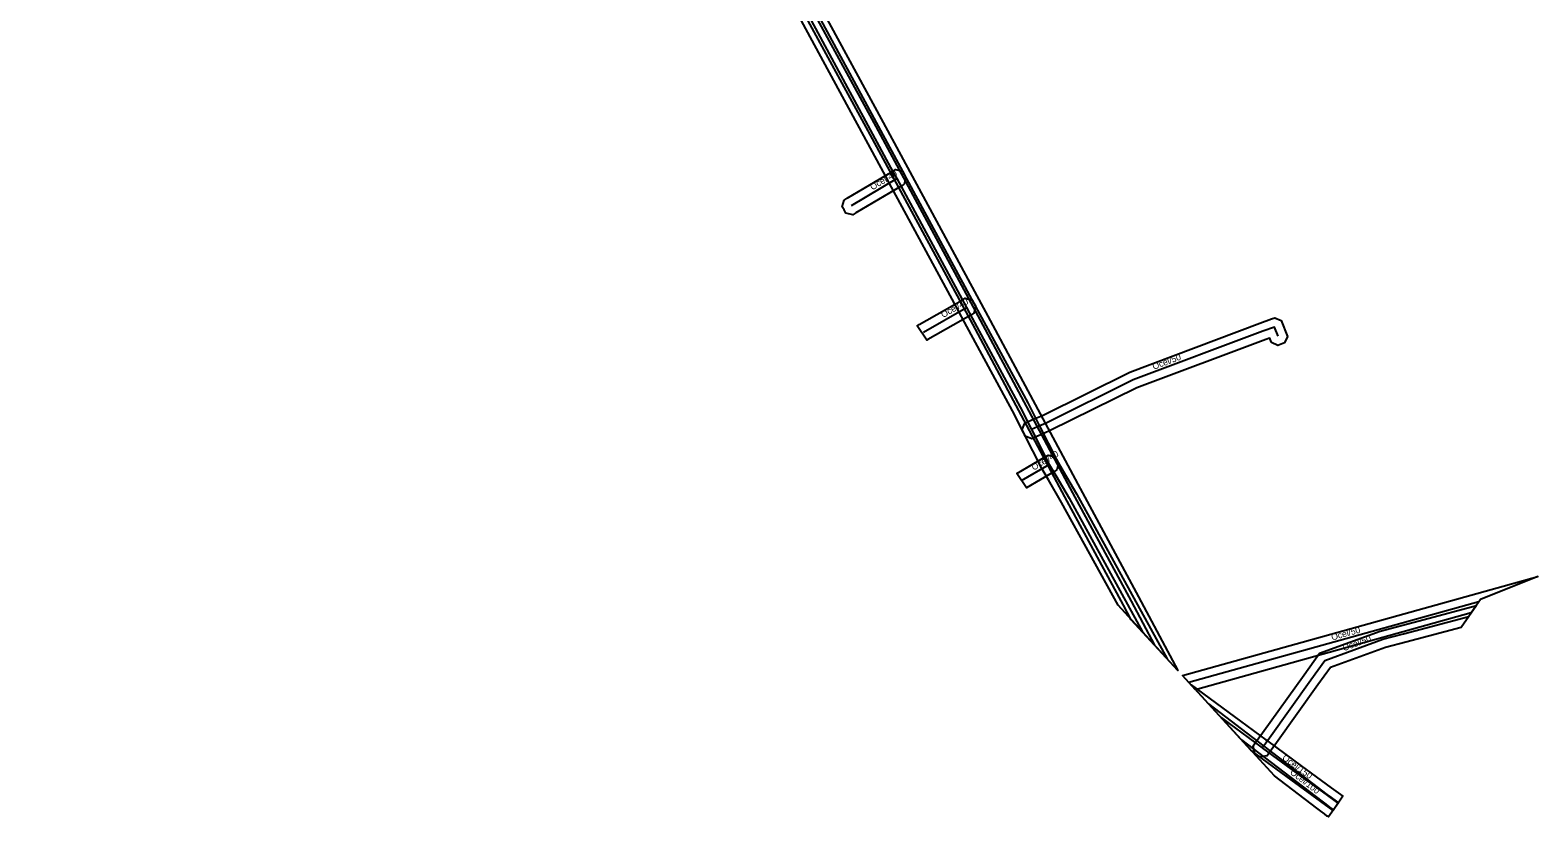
# Model space of a CAD drawing. Extents: x -749340 to -748632, y -965391 to -964902.
# Drawn here: x -748807.4 to -748632.1, y -965391.4 to -965299.9 of the extents above; entities that cross this region are included whole.
import ezdxf

# ---------------------------------------------------------------- set-up
doc = ezdxf.new("R2010")
doc.units = 0
for name, color, linetype in [('1', 7, 'Continuous'), ('18', 7, 'Continuous'), ('20', 7, 'Continuous'), ('28', 7, 'Continuous'), ('30', 7, 'Continuous')]:
    doc.layers.add(name, color=color, linetype=linetype)

msp = doc.modelspace()

# ---------------------------------------------------------------- linework, layer by layer
at = {"layer": '1'}
for points in [[(-748716.01, -965297.73), (-748706.19, -965315.89), (-748705.75, -965316.7), (-748697.65, -965331.68), (-748696.99, -965332.9), (-748691.39, -965343.25), (-748690.06, -965345.87), (-748688.01, -965349.91), (-748687.26, -965351.19), (-748685.72, -965353.82), (-748675.2, -965372.98), (-748680.9, -965366.77), (-748687.46, -965354.81), (-748688.99, -965352.2), (-748689.76, -965350.87), (-748691.84, -965346.78), (-748693.16, -965344.18), (-748698.75, -965333.85), (-748699.41, -965332.63), (-748707.51, -965317.65), (-748707.95, -965316.84), (-748717.7, -965298.81)], [(-748715.47, -965297.31), (-748708.2, -965310.65), (-748696.03, -965333.14), (-748685.32, -965353.2), (-748678.5, -965365.8), (-748673.94, -965374.35), (-748679.36, -965368.45), (-748680.26, -965366.75), (-748687.08, -965354.15), (-748697.8, -965334.09), (-748709.95, -965311.6), (-748717.16, -965298.4)]]:
    msp.add_lwpolyline(points, dxfattribs=at)
for points in [[(-748712.76, -965319.66), (-748712.4, -965319.44), (-748707.14, -965316.32), (-748706.79, -965316.1), (-748705.98, -965316.31), (-748705.77, -965316.66), (-748705.56, -965317.02), (-748705.76, -965317.82), (-748706.12, -965318.03), (-748711.38, -965321.16), (-748711.73, -965321.37), (-748712.54, -965321.17), (-748712.75, -965320.81), (-748712.96, -965320.46)], [(-748703.03, -965335.88), (-748703.12, -965335.93), (-748704.25, -965334.27), (-748704.02, -965334.14), (-748699.02, -965331.29), (-748698.66, -965331.08), (-748697.86, -965331.3), (-748697.66, -965331.66), (-748697.45, -965332.02), (-748697.67, -965332.82), (-748698.03, -965333.03)], [(-748663.07, -965336.23), (-748663.22, -965335.84), (-748663.27, -965335.7), (-748663.7, -965335.86), (-748678.72, -965341.48), (-748688.85, -965346.5), (-748689.86, -965346.94), (-748690.55, -965347.24), (-748690.93, -965347.41), (-748691.7, -965347.11), (-748691.87, -965346.73), (-748692.03, -965346.35), (-748691.73, -965345.58), (-748691.35, -965345.41), (-748690.66, -965345.11), (-748689.69, -965344.69), (-748679.52, -965339.65), (-748664.4, -965333.99), (-748663.05, -965333.48), (-748662.66, -965333.34), (-748661.91, -965333.68), (-748661.76, -965334.06), (-748661.35, -965335.12), (-748661.2, -965335.51), (-748661.54, -965336.27), (-748661.93, -965336.42), (-748662.32, -965336.56)], [(-748688.38, -965351.25), (-748691.55, -965353.11), (-748692.67, -965351.45), (-748689.39, -965349.53), (-748689.04, -965349.32), (-748688.23, -965349.52), (-748688.02, -965349.88), (-748687.81, -965350.24), (-748688.02, -965351.04)], [(-748671.89, -965376.59), (-748673.41, -965374.94), (-748632.08, -965363.43), (-748638.74, -965366.09), (-748639.84, -965367.67)], [(-748639.23, -965366.79), (-748641.01, -965369.34), (-748644.8, -965370.35), (-748647.43, -965371.05), (-748649.81, -965371.68), (-748656.2, -965374.02), (-748657.65, -965376.03), (-748662.48, -965382.77), (-748663.31, -965383.93), (-748663.55, -965384.27), (-748664.36, -965384.41), (-748664.7, -965384.17), (-748665.04, -965383.93), (-748665.18, -965383.11), (-748664.94, -965382.77), (-748664.11, -965381.61), (-748659.27, -965374.86), (-748657.47, -965372.35), (-748650.41, -965369.77), (-748647.94, -965369.12), (-748645.31, -965368.42)], [(-748664.89, -965384.03), (-748665.45, -965383.62), (-748672.39, -965376.04), (-748667.38, -965379.72), (-748663.7, -965382.42), (-748663.53, -965382.55), (-748663.49, -965382.57), (-748659.59, -965385.43), (-748656.12, -965387.98), (-748654.76, -965388.98), (-748655.9, -965390.62), (-748657.31, -965389.59), (-748660.78, -965387.05), (-748664.68, -965384.19), (-748664.71, -965384.16)], [(-748657.8, -965390.35), (-748662.7, -965386.61), (-748670.38, -965378.23), (-748670.36, -965378.25), (-748663.95, -965383.15), (-748656.6, -965388.76), (-748656.12, -965389.11), (-748655.7, -965389.42), (-748655.37, -965389.67), (-748655.28, -965389.73), (-748656.43, -965391.37), (-748656.46, -965391.34), (-748656.56, -965391.28), (-748656.89, -965391.03), (-748657.31, -965390.72)]]:
    msp.add_lwpolyline(points, close=True, dxfattribs=at)
at = {"layer": '18'}
for points in [[(-748824.79, -965209.23), (-748798.49, -965229.11), (-748790.82, -965234.91), (-748784.9, -965239.18), (-748781.61, -965241.24), (-748747.83, -965265.97), (-748743.95, -965268.77), (-748739.09, -965273.27), (-748727.78, -965283.74), (-748724.38, -965288.26), (-748720.98, -965292.78), (-748719.53, -965294.71), (-748716.86, -965298.27), (-748707.07, -965316.36), (-748706.63, -965317.17), (-748698.53, -965332.16), (-748697.87, -965333.38), (-748692.28, -965343.72), (-748690.95, -965346.33), (-748688.89, -965350.39), (-748688.12, -965351.69), (-748686.59, -965354.32), (-748678.05, -965369.87)], [(-748711.89, -965320.3), (-748706.63, -965317.17)], [(-748703.53, -965335.01), (-748698.53, -965332.16)], [(-748662.29, -965335.48), (-748662.7, -965334.42), (-748664.05, -965334.92), (-748679.12, -965340.57), (-748689.27, -965345.6), (-748690.26, -965346.03), (-748690.95, -965346.33)], [(-748692.11, -965352.28), (-748688.89, -965350.39)], [(-748638.94, -965366.38), (-748672.65, -965375.77)], [(-748666.54, -965382.42), (-748664.55, -965383.94), (-748657.2, -965389.56), (-748656.72, -965389.91), (-748656.29, -965390.23), (-748655.96, -965390.47), (-748655.87, -965390.54), (-748655.86, -965390.55)]]:
    msp.add_lwpolyline(points, dxfattribs=at)
at = {"layer": '28'}
for points in [[(-748816.65, -965214.51), (-748766.66, -965251.35), (-748757.66, -965257.99), (-748743.56, -965268.19), (-748739.14, -965272.2), (-748738.6, -965272.7), (-748730.9, -965279.9), (-748727.31, -965283.26), (-748718.98, -965294.32), (-748716.31, -965297.86), (-748709.08, -965311.12), (-748696.92, -965333.61), (-748686.2, -965353.68), (-748679.38, -965366.28), (-748676.65, -965371.4)], [(-748664.12, -965383.35), (-748663.29, -965382.19), (-748658.46, -965375.45), (-748656.84, -965373.18), (-748650.11, -965370.73), (-748647.69, -965370.08), (-748645.05, -965369.38), (-748640.12, -965368.07)], [(-748668.92, -965379.83), (-748667.98, -965380.52), (-748664.29, -965383.22), (-748664.12, -965383.35), (-748664.08, -965383.38), (-748660.19, -965386.24), (-748656.71, -965388.79), (-748655.33, -965389.8)]]:
    msp.add_lwpolyline(points, dxfattribs=at)

# ---------------------------------------------------------------- texts
at = {"layer": '20'}
for s, rotation, p in [('Ocel/40', 30.7438, (-748709.46, -965318.54)), ('Ocel/40', 29.6733, (-748701.23, -965333.38)), ('Ocel/50', 20.5156, (-748676.74, -965339.4)), ('Ocel/40', 30.4642, (-748690.7, -965351.13)), ('Ocel/50', 15.5597, (-748655.99, -965370.87)), ('Ocel/100', 322.6545, (-748660.97, -965386.33))]:
    msp.add_text(s, height=0.75, rotation=rotation, dxfattribs=at).set_placement(p)
at = {"layer": '30'}
for s, rotation, p in [('Ocel/50', 20.0412, (-748654.64, -965372.11)), ('Ocel/150', 323.7366, (-748661.88, -965384.65))]:
    msp.add_text(s, height=0.75, rotation=rotation, dxfattribs=at).set_placement(p)

doc.saveas('drawing.dxf')
